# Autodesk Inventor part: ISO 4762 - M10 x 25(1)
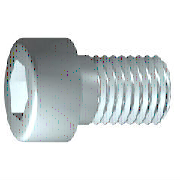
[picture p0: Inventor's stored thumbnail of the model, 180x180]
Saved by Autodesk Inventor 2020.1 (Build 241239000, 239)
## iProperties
Created: 2019-01
Part Number: ISO 4762 - M10 x 25(1)
Material: Edelstahl, 440C
Description: Innensechskantschraube
Document SubType Name: Modeling
Standard: ISO 4762
Designer: lutzd
Standard Revision: Fourth edition 2004-03-01
Standards Organization: ISO
Language: de-DE
Size Designation: M10 x 25
Categories: <MemberInstance><Categories><Category DisplayName="Verbindungselemente" InternalName="e4da775c-781d-43d5-af7c-5136215cf5a6" Mnemonic="FSTN"><Category DisplayNam
Mass: 28.0251 g
Surface Area: 18.0242 cm^2
Volume: 3.61614 cm^3
Density: 7.75 g/cm^3
Appearance: Halbpoliert
IsCustomPart: 0
Author: lutzd
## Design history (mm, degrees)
workplane "Work Plane1"
fillet "Fillet2" dims "d30" = 0.1 (= R)
sketch "Skizze1"
  geometry: L1 (-2.333, 0)-(25, 0); L2 (25, 0)-(25, 5); L3 (25, 5)-(3.75, 5); L4 (3.75, 5)-(2.83, 5); L5 (2.83, 5)-(0, 5); L6 (0, 5)-(0, 8); L7 (0, 8)-(-10, 8); L8 (-10, 8)-(-10, 4.619); L9 (-10, 4.619)-(-5, 4.619); L10 (-5, 4.619)-(-2.333, 0); L11 (-17, 0)-(32, 0) reference; L12 (0, -1.6)-(0, 9.6) reference; L13 (3.75, 5)-(0, 5)
  constraints: 22 end point, 6 parallel, 2 collinear, 2 perpendicular, 1 horizontal, 1 point on line
  dimensions: "d1" = 21.25 distance from line of L3.end L2 (= GEL); "d2" = 0.92028 distance of L4.end L3.end (computed from GAL); "d3" = 10 distance between parallel lines of L8 L6 (= KOH); "d4" = 5 distance of L8.end L9.end (= INTI); "d5" = 60 deg angle of L10 L1; "d6" = 10 diameter of L3 L1 (= GD); "d7" = 10 diameter of L5 L1 (= BDM); "d8" = 9.2376 diameter of L9 L1 (= 1.1547 x SW); "d9" = 16 diameter of L7 L1 (= KOD); "d26" = 25 distance between parallel lines of L12 L2 (= NLG)
revolve "Körper" sketch "Skizze1" stored, may be unused: angle "d10" = 90 deg
sketch "Skizze2"
  geometry: L1 (0, -11.2)-(0, 11.2) reference; L2 (-11.2, 0)-(11.2, 0) reference; L3 (4.619, 0)-(2.309, -4); L4 (2.309, -4)-(-2.309, -4); L5 (-2.309, -4)-(-4.619, 0); L6 (-4.619, 0)-(-2.309, 4); L7 (-2.309, 4)-(2.309, 4); L8 (2.309, 4)-(4.619, 0); 2 further points
  constraints: 12 end point, 1 coincident, 1 horizontal alignment, 1 point on line, 12 other
extrude "Loch" join sketch "Skizze2" stored distance "d11" = 10; taper "d12" = 0 deg
body "Solid1"
fillet "Rundung1" dims "d17" = 1 (= RR)
feature "Gewinde" dims "d13" = 21.25 (= GEL), "d14" = 0
chamfer "Fase1" distance "d15" = 0.92018 (= -0.5 x SPD + 0.5 x GD); stored, may be unused: second distance "d16" = 0.92018 (= GUL), angle "d27" = 45 deg
other parameters: "GD" = 10 [user parameter; used in 2 equation terms], "NLG" = 25 [user parameter; used in 1 equation term], "GEL" = 21.25 [user parameter; used in 2 equation terms], "KOD" = 16 [user parameter; used in 1 equation term], "KOH" = 10 [user parameter; used in 1 equation term], "INTI" = 5 [user parameter; used in 1 equation term], "GAL" = 0.92018 (= 0.61345 x PTC) [user parameter; used in 1 equation term], "GUL" = 0.92018 (= 0.61345 x PTC) [user parameter; used in 1 equation term], "BDM" = 10 (= NND) [user parameter; used in 1 equation term], "SW" = 8 [user parameter; used in 2 equation terms], "RR" = 1 [user parameter; used in 1 equation term], "SPD" = 8.15965 (= NND - 1.2269 x PTC) [user parameter; used in 1 equation term], "d19" = 0, "d28" = 0, "d29" = 0, "R" = 0.1 [user parameter; used in 1 equation term], "TOA" = 30 deg [user parameter], "GD1" = 8.15965 (= THREADDIA - 1.2269 x PTC) [user parameter], "FAWI" = 45 deg [user parameter], "TPU" = 6.66667 (computed from PTC) [user parameter], "PTC" = 1.5 [user parameter; used in 5 equation terms], "E0" = 9.24 (= 1.155 x SW) [user parameter]
